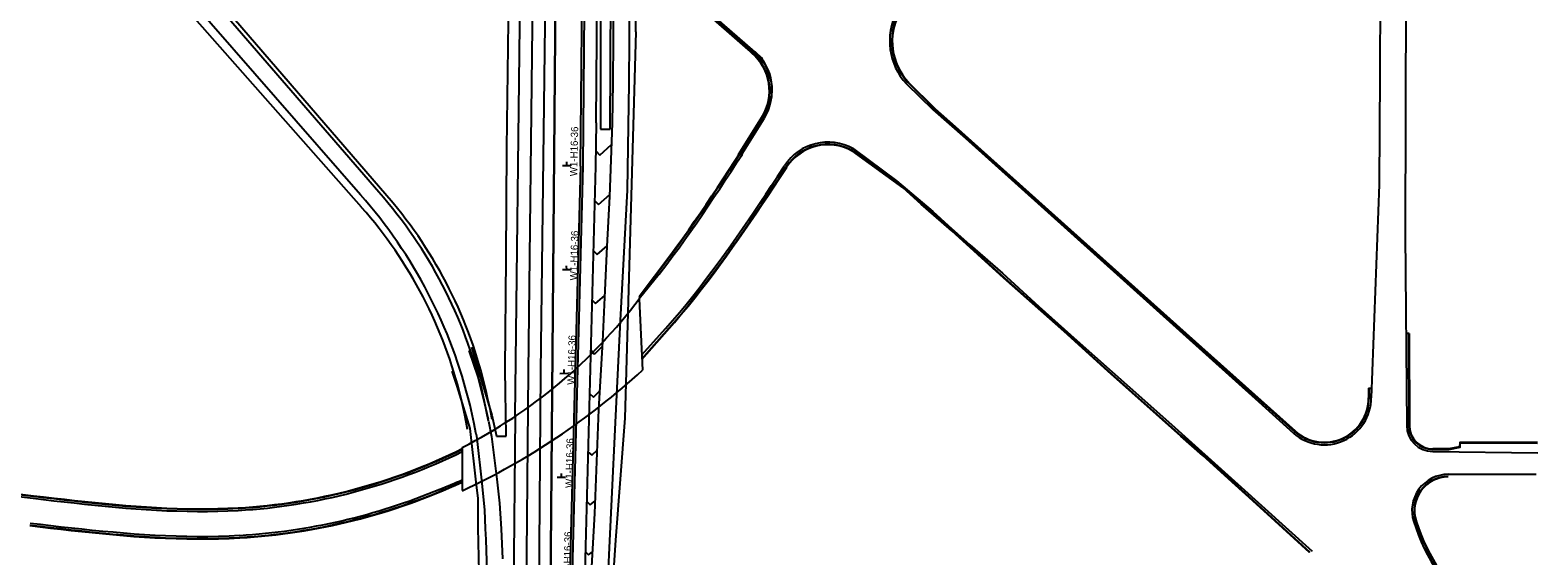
# Model space of a CAD drawing. Extents: x 1691089 to 1704871, y 694247 to 736350.
# Drawn here: x 1700893 to 1702343, y 708976 to 709482 of the extents above; entities that cross this region are included whole.
import ezdxf

# ---------------------------------------------------------------- set-up
doc = ezdxf.new("R2010")
doc.units = 0
for name, color, linetype in [('BR_X_Slab_Object', 7, 'Continuous'), ('MT_P_Channelizing_Line', 7, 'Continuous'), ('MT_P_Drums', 7, 'Continuous'), ('MT_P_Edge_Line', 7, 'Continuous'), ('PM_X_Channelizing_Line', 7, 'Continuous'), ('PM_X_Chevron_Line', 7, 'Continuous'), ('PM_X_CL_Dashed', 7, 'Continuous'), ('PM_X_Edge_Line', 7, 'Continuous'), ('PV_X_Curb', 7, 'Continuous'), ('PV_X_EOP', 7, 'Continuous'), ('PV_X_Shoulder', 7, 'Continuous'), ('RW_X_CL', 7, 'Continuous'), ('SC_Scratch1', 7, 'Continuous'), ('SC_Scratch3', 7, 'Continuous'), ('SN_P_Signs', 7, 'Continuous')]:
    doc.layers.add(name, color=color, linetype=linetype)

msp = doc.modelspace()

# ---------------------------------------------------------------- linework, layer by layer
at = {"layer": 'BR_X_Slab_Object'}
for p, q in [((1701478.8, 709223.9), (1701481.8, 709155.1)), ((1701308.5, 709080.8), (1701308.4, 709039.4))]:
    msp.add_line(p, q, dxfattribs=at)
for centre, radius, start, end in [((1701087.2, 709517), 489.1, 296.9039, 323.1906), ((1701022.3, 709653.8), 678.1, 294.9545, 312.6565)]:
    msp.add_arc(centre, radius, start, end, dxfattribs=at)
at = {"layer": 'MT_P_Channelizing_Line'}
for p, q in [((1701437.2, 709393.1), (1701436.8, 709351.4)), ((1701436.8, 709351.4), (1701426.4, 708961.4))]:
    msp.add_line(p, q, dxfattribs=at)
at = {"layer": 'MT_P_Drums'}
for q in [(1701430.3, 710278.4), (1701411.9, 708961.6)]:
    msp.add_line((1701422.3, 709351.5), q, dxfattribs=at)
at = {"layer": 'MT_P_Edge_Line'}
msp.add_line((1701437.2, 709393.1), (1701444.8, 710278.3), dxfattribs=at)
msp.add_lwpolyline([(1701414.4, 708961.6), (1701424.8, 709351.5), (1701474.5, 715147.9), (1701474.6, 715157.9), (1701474.7, 715167.9), (1701474.8, 715177.9), (1701474.9, 715187.9), (1701474.9, 715198), (1701475, 715208), (1701475, 715218), (1701475, 715228.1), (1701475, 715238.2), (1701475, 715248.3), (1701474.9, 715258.3), (1701474.8, 715268.4), (1701474.7, 715278.5), (1701474.5, 715288.6), (1701474.3, 715298.7), (1701474.1, 715308.8), (1701473.8, 715318.9), (1701473.5, 715329), (1701473.2, 715339.2), (1701472.7, 715349.3), (1701472.7, 715349.4)], dxfattribs=at)
at = {"layer": 'PM_X_Channelizing_Line'}
for p, q in [((1701445.7, 709225.1), (1701447.9, 709274.2)), ((1701443.7, 709182.7), (1701445.7, 709225.1)), ((1701439.9, 709117.3), (1701443.7, 709182.7)), ((1701435.9, 709017.3), (1701439.9, 709117.3)), ((1701359.3, 709111), (1701357.3, 708878.3)), ((1701336.5, 709091.3), (1701341.9, 709050.1)), ((1701341.9, 709050.1), (1701344.4, 709027.2)), ((1701344.4, 709027.2), (1701345.8, 709002.3)), ((1701431.8, 708942.4), (1701435.9, 709017.3)), ((1701345.8, 709002.3), (1701347.3, 708973.4))]:
    msp.add_line(p, q, dxfattribs=at)
msp.add_lwpolyline([(1701447.9, 709274.2), (1701450.3, 709322.3), (1701453, 709393)], dxfattribs=at)
at = {"layer": 'PM_X_Chevron_Line'}
for p, q in [((1701437, 709366.1), (1701440.8, 709362.2)), ((1701440.8, 709362.2), (1701452.2, 709372.3)), ((1701439.5, 709314.7), (1701450.4, 709324.2)), ((1701435.9, 709318.2), (1701439.5, 709314.7)), ((1701434.6, 709269.9), (1701438.3, 709266.4)), ((1701438.3, 709266.4), (1701447.9, 709274.9)), ((1701433.4, 709222.5), (1701436.8, 709219.2)), ((1701436.8, 709219.2), (1701445.8, 709226.9)), ((1701432.1, 709174.6), (1701435.6, 709170.5)), ((1701435.6, 709170.5), (1701443.4, 709178.2)), ((1701431, 709132.7), (1701434.6, 709129.2)), ((1701434.6, 709129.2), (1701441, 709135.6)), ((1701429.4, 709076.6), (1701433, 709073.3)), ((1701433, 709073.3), (1701438.4, 709078.1)), ((1701428.2, 709028.6), (1701431.4, 709025.4)), ((1701431.4, 709025.4), (1701436.4, 709029.5)), ((1701426.9, 708980.4), (1701429.9, 708977.4)), ((1701429.9, 708977.4), (1701433.9, 708980.3))]:
    msp.add_line(p, q, dxfattribs=at)
at = {"layer": 'PM_X_CL_Dashed'}
for p, q in [((1701376.2, 709513.9), (1701371.9, 709153.6)), ((1701371.9, 709153.6), (1701369.4, 708873))]:
    msp.add_line(p, q, dxfattribs=at)
at = {"layer": 'PM_X_Edge_Line'}
for p, q in [((1701453.6, 709431.6), (1701455.3, 709652.5)), ((1701469, 709431.5), (1701470.7, 709652.4)), ((1701359.3, 709111), (1701364.2, 709514)), ((1701388.2, 709513.8), (1701383.9, 709153.6)), ((1701453, 709393), (1701453.6, 709431.7)), ((1701467.3, 709328.4), (1701469, 709431.5)), ((1701460.7, 709202.8), (1701467.3, 709328.4)), ((1701457.3, 709131.3), (1701460.7, 709202.8)), ((1701383.9, 709153.6), (1701381.4, 708873)), ((1701451.1, 709004.3), (1701457.3, 709131.3)), ((1701333.9, 709106.2), (1701336.5, 709091.3)), ((1701444.7, 708876.8), (1701451.1, 709004.3))]:
    msp.add_line(p, q, dxfattribs=at)
msp.add_lwpolyline([(1701321.9, 709093.5), (1701322.4, 709089.4), (1701327.2, 709046.4), (1701328.5, 709033.1), (1701329.9, 709020.8), (1701330.6, 709002.3), (1701331.2, 708992.2), (1701332.4, 708950.8), (1701333.5, 708881.3), (1701334.1, 708822.9), (1701336, 708716.7), (1701337.6, 708568.1), (1701339.8, 708456.3), (1701343, 708267.7), (1701345.1, 708154.5), (1701348.7, 707936.7), (1701349.3, 707853.3), (1701350.4, 707631.1), (1701349.9, 707475), (1701348.9, 707313), (1701348.7, 707061.8)], dxfattribs=at)
at = {"layer": 'PV_X_Curb'}
for p, q in [((1701574.3, 709362.8), (1701596.7, 709398.7)), ((1701574.7, 709362.6), (1701597.1, 709398.4)), ((1701613.3, 709340.3), (1701620.1, 709350.7)), ((1701613.7, 709340), (1701620.7, 709350.5)), ((1702219.1, 709190.5), (1702216.6, 709190.4)), ((1702180.2, 709137.7), (1702180.2, 709128.4)), ((1702180.2, 709137.7), (1702182.7, 709137.7)), ((1702180.7, 709137.7), (1702180.7, 709128.4)), ((1700681.9, 709059.5), (1700896, 709034.3)), ((1700681.9, 709059), (1700896, 709033.8))]:
    msp.add_line(p, q, dxfattribs=at)
for points in [[(1701504.5, 709532.7), (1701595.7, 709453)], [(1701504.8, 709533), (1701596, 709453.4)], [(1701737.2, 709432.2), (1701763.5, 709406.1), (1701782.5, 709388.9), (1702004.6, 709189.9), (1702109.4, 709095.9)], [(1702109.8, 709096.3), (1702004.9, 709190.3), (1701782.8, 709389.2), (1701763.8, 709406.4), (1701737.5, 709432.5)], [(1701478.7, 709226), (1701509.2, 709266.6), (1701515, 709274.4), (1701520.7, 709282.3), (1701526.3, 709290.3), (1701531.9, 709298.4), (1701537.5, 709306.5), (1701543, 709314.6), (1701548.5, 709322.8), (1701554, 709331.1), (1701559.4, 709339.4), (1701564.9, 709347.7), (1701570.3, 709356), (1701575.8, 709364.4)], [(1701478.7, 709225.2), (1701509.6, 709266.3), (1701515.4, 709274.1), (1701521.1, 709282.1), (1701526.8, 709290), (1701532.4, 709298.1), (1701537.9, 709306.2), (1701543.4, 709314.4), (1701548.9, 709322.6), (1701554.4, 709330.8), (1701559.9, 709339.1), (1701565.3, 709347.4), (1701570.8, 709355.8), (1701576.2, 709364.1)], [(1702123.5, 708979.6), (1702090.4, 709009.7), (1702068.9, 709029.3), (1702048.9, 709047.5), (1702020.8, 709073), (1701999.7, 709091.6), (1701929.3, 709154.2), (1701887.4, 709192.2), (1701829.5, 709243.6), (1701779.5, 709289.2), (1701749.8, 709315), (1701732.5, 709330.7), (1701683.5, 709366.1)], [(1701683.8, 709366.5), (1701732.8, 709331.1), (1701750.1, 709315.3), (1701779.8, 709289.6), (1701829.9, 709244), (1701887.7, 709192.5), (1701929.6, 709154.6), (1702000, 709092), (1702021.2, 709073.3), (1702049.2, 709047.9), (1702069.2, 709029.7), (1702090.8, 709010.1), (1702123.8, 708980)], [(1701481.3, 709166.2), (1701512.2, 709201.5), (1701518.9, 709209.2), (1701525.4, 709217.1), (1701531.7, 709225), (1701538, 709233), (1701544.2, 709241), (1701550.3, 709249.2), (1701556.3, 709257.3), (1701562.3, 709265.5), (1701568.1, 709273.7), (1701573.9, 709282), (1701579.6, 709290.3), (1701585.3, 709298.6), (1701591, 709306.9), (1701596.6, 709315.3), (1701602.2, 709323.6), (1701607.7, 709331.9), (1701613.3, 709340.3)], [(1701481.3, 709165.5), (1701512.6, 709201.1), (1701519.2, 709208.9), (1701525.7, 709216.8), (1701532.1, 709224.7), (1701538.4, 709232.7), (1701544.6, 709240.7), (1701550.7, 709248.9), (1701556.7, 709257), (1701562.7, 709265.2), (1701568.5, 709273.4), (1701574.3, 709281.7), (1701580.1, 709290), (1701585.7, 709298.3), (1701591.4, 709306.6), (1701597, 709315), (1701602.6, 709323.3), (1701608.1, 709331.6), (1701613.7, 709340)], [(1702218.6, 709190.4), (1702218.9, 709101.8)], [(1702219.1, 709190.5), (1702219.4, 709101.9)], [(1702342.7, 709085.4), (1702286.4, 709085.6), (1702267.9, 709085.6), (1702267.8, 709081.4), (1702257.4, 709079.4), (1702242, 709079.4)], [(1702242, 709078.9), (1702257.5, 709078.9), (1702268.2, 709081), (1702268.4, 709085.1), (1702286.4, 709085.1), (1702342.7, 709084.9)], [(1700896, 709034.3), (1700905.9, 709033.2), (1700915.9, 709032), (1700925.8, 709030.9), (1700935.7, 709029.8), (1700945.5, 709028.7), (1700955.4, 709027.7), (1700965.3, 709026.7), (1700975.2, 709025.8), (1700985, 709024.9), (1700994.9, 709024.2), (1701004.7, 709023.5), (1701014.5, 709022.9), (1701024.4, 709022.4), (1701034.2, 709022.1), (1701044, 709021.8), (1701053.8, 709021.7), (1701063.6, 709021.7), (1701073.4, 709021.9), (1701083.1, 709022.2), (1701093, 709022.7)], [(1700896, 709033.8), (1700905.9, 709032.7), (1700915.8, 709031.5), (1700925.7, 709030.4), (1700935.6, 709029.3), (1700945.5, 709028.2), (1700955.4, 709027.2), (1700965.2, 709026.2), (1700975.1, 709025.3), (1700985, 709024.4), (1700994.8, 709023.7), (1701004.7, 709023), (1701014.5, 709022.4), (1701024.3, 709021.9), (1701034.2, 709021.6), (1701044, 709021.3), (1701053.8, 709021.2), (1701063.6, 709021.2), (1701073.4, 709021.4), (1701083.2, 709021.7), (1701093, 709022.2)], [(1700892.6, 709005.5), (1700902.6, 709004.4), (1700912.5, 709003.2), (1700922.5, 709002.1), (1700932.5, 709000.9), (1700942.5, 708999.9), (1700952.5, 708998.8), (1700962.5, 708997.8), (1700972.6, 708996.9), (1700982.6, 708996), (1700992.7, 708995.2), (1701002.8, 708994.5), (1701013, 708993.9), (1701023.1, 708993.4), (1701033.3, 708993.1), (1701043.5, 708992.8), (1701053.7, 708992.7), (1701063.9, 708992.7), (1701074.1, 708992.9), (1701084.3, 708993.2), (1701094.4, 708993.7)], [(1700892.7, 709006), (1700902.6, 709004.9), (1700912.6, 709003.7), (1700922.5, 709002.6), (1700932.5, 709001.4), (1700942.5, 709000.4), (1700952.5, 708999.3), (1700962.6, 708998.3), (1700972.6, 708997.4), (1700982.7, 708996.5), (1700992.8, 708995.7), (1701002.9, 708995), (1701013, 708994.4), (1701023.1, 708993.9), (1701033.3, 708993.6), (1701043.5, 708993.3), (1701053.7, 708993.2), (1701063.9, 708993.2), (1701074.1, 708993.4), (1701084.3, 708993.7), (1701094.4, 708994.2)]]:
    msp.add_lwpolyline(points, dxfattribs=at)
for centre, radius, start, end in [((1701779.6, 709471.7), 58, 152.245, 223.002), ((1701779.6, 709471.7), 57.5, 152.245, 223.002), ((1701556.4, 709423.9), 47.5, 327.9635, 49.815), ((1701556.4, 709423.9), 48, 327.9635, 49.8927), ((1701559, 709425.8), 47.5, 326.9156, 48.7671), ((1701660.3, 709324.6), 48, 60.7984, 146.977), ((1701660.3, 709324.6), 47.5, 60.8165, 146.8745), ((1702137.7, 709128.3), 43, 228.858, 0.2254), ((1702137.7, 709128.3), 42.5, 228.858, 0.2562), ((1702241.9, 709101.9), 23, 180.2308, 270.2308), ((1702241.9, 709101.9), 22.5, 180.2308, 270.2308), ((1701060.8, 709580.2), 558.5, 273.2963, 296.3321), ((1701060.8, 709580.2), 559, 273.2963, 296.3066), ((1701060.8, 709580.2), 587, 273.2963, 294.9549), ((1701060.8, 709580.2), 587.5, 273.2963, 294.932), ((1702256.9, 709019.9), 33, 90.1804, 197.7824), ((1702256.9, 709019.9), 32.5, 90.1804, 197.7824), ((1702416, 709070.7), 200, 197.732, 228.7856), ((1702416, 709070.7), 199.5, 197.732, 228.7856)]:
    msp.add_arc(centre, radius, start, end, dxfattribs=at)
at = {"layer": 'PV_X_EOP'}
for p, q in [((1701446.5, 715148.2), (1701323.4, 700783.8)), ((1701446.5, 715148.2), (1701323.4, 700783.8)), ((1701446.5, 715148.2), (1701323.4, 700783.8)), ((1701446.5, 715148.2), (1701323.4, 700783.8)), ((1701441.6, 709583.3), (1701441.6, 709387.2)), ((1701450.8, 709387.2), (1701451.9, 709574.3)), ((1701210.7, 709323.9), (1701047, 709511.5)), ((1701228.2, 709326.4), (1701069.3, 709510.2)), ((1701576.4, 709361.5), (1701598.8, 709397.4)), ((1701441.6, 709387.2), (1701450.8, 709387.2)), ((1701611.6, 709341.4), (1701618.6, 709351.8)), ((1701497.8, 709247.5), (1701478.8, 709223.9)), ((1700681.6, 709057), (1700895.7, 709031.8))]:
    msp.add_line(p, q, dxfattribs=at)
for points in [[(1702236.5, 711634.6), (1702234.2, 711544.9), (1702233.5, 711441.5), (1702227.9, 711277.7), (1702226.4, 711103), (1702225.5, 711002.5), (1702224.4, 710870.4), (1702223.7, 710704.5), (1702222.7, 710562.6), (1702221.6, 710366.2), (1702220.3, 710180.7), (1702218.7, 709978.6), (1702217.3, 709834.2), (1702216.7, 709707.1), (1702216, 709519), (1702215.3, 709285.9), (1702216.9, 709101.8)], [(1702196.2, 711603), (1702197.1, 711593), (1702198.4, 711561.8), (1702203.2, 711284.2), (1702203.9, 711216.5), (1702203.6, 711180.6), (1702203.3, 711141.8), (1702200.2, 710747.3), (1702198.5, 710484), (1702195.7, 710156.1), (1702195.4, 710077.5), (1702194.4, 709958.4), (1702193.1, 709774.7), (1702191.7, 709594.1), (1702191.1, 709439.8), (1702190.5, 709333.9), (1702182.7, 709128.4)], [(1701506.2, 709534.5), (1701597.3, 709454.9)], [(1701735.7, 709430.8), (1701761.2, 709406), (1701792.4, 709378.3), (1702074.3, 709124.9), (1702108.1, 709094.4)], [(1701497.8, 709247.5), (1701505.4, 709257.3), (1701511.2, 709265.1), (1701517, 709273), (1701522.7, 709280.9), (1701528.4, 709288.9), (1701534, 709297), (1701539.6, 709305.1), (1701545.1, 709313.2), (1701550.6, 709321.5), (1701556.1, 709329.7), (1701561.5, 709338), (1701567, 709346.3), (1701572.4, 709354.7), (1701577.9, 709363)], [(1701684.7, 709368.2), (1701726.2, 709337.5), (1701761, 709308), (1701776, 709294.3), (1701796.8, 709275.7), (1701828.2, 709248.4), (1701863.1, 709216.5), (1701899.6, 709183.8), (1701950.5, 709138.3), (1701990.8, 709102.7), (1702054.4, 709045.4), (1702125.8, 708980.8)], [(1701481.1, 709169.9), (1701504, 709195.1), (1701510.7, 709202.8), (1701517.3, 709210.5), (1701523.8, 709218.4), (1701530.2, 709226.3), (1701536.5, 709234.2), (1701542.6, 709242.3), (1701548.7, 709250.3), (1701554.7, 709258.5), (1701560.6, 709266.7), (1701566.5, 709274.9), (1701572.3, 709283.1), (1701578, 709291.4), (1701583.7, 709299.7), (1701589.3, 709308), (1701594.9, 709316.4), (1701600.5, 709324.7), (1701606, 709333), (1701611.6, 709341.4)], [(1701333.9, 709106.2), (1701329.7, 709126.3), (1701327.6, 709135.3)], [(1701321.9, 709093.5), (1701321.7, 709094.7), (1701320, 709103.6), (1701318.1, 709112.5), (1701316, 709121.4)], [(1702242, 709076.9), (1702343, 709075.7)], [(1702256.8, 709054.9), (1702341.5, 709055.2)], [(1700895.7, 709031.8), (1700905.7, 709030.7), (1700915.6, 709029.5), (1700925.5, 709028.4), (1700935.4, 709027.3), (1700945.3, 709026.2), (1700955.2, 709025.2), (1700965, 709024.2), (1700974.9, 709023.3), (1700984.8, 709022.4), (1700994.7, 709021.7), (1701004.5, 709021), (1701014.4, 709020.4), (1701024.3, 709019.9), (1701034.1, 709019.6), (1701044, 709019.3), (1701053.8, 709019.2), (1701063.6, 709019.2), (1701073.4, 709019.4), (1701083.2, 709019.7), (1701093.1, 709020.2)], [(1700892.9, 709008), (1700902.9, 709006.8), (1700912.8, 709005.7), (1700922.8, 709004.5), (1700932.7, 709003.4), (1700942.7, 709002.3), (1700952.7, 709001.3), (1700962.8, 709000.3), (1700972.8, 708999.4), (1700982.8, 708998.5), (1700992.9, 708997.7), (1701003, 708997), (1701013.1, 708996.4), (1701023.2, 708995.9), (1701033.4, 708995.6), (1701043.5, 708995.3), (1701053.7, 708995.2), (1701063.8, 708995.2), (1701074, 708995.4), (1701084.2, 708995.7), (1701094.3, 708996.2)]]:
    msp.add_lwpolyline(points, dxfattribs=at)
for centre, radius, start, end in [((1701779.6, 709471.7), 60, 152.245, 223.002), ((1701556.4, 709423.9), 50, 327.9635, 49.9558), ((1701660.3, 709324.6), 50, 60.8165, 146.958), ((1700856.4, 709010.9), 472.7, 13.5158, 41.458), ((1700893.8, 709031), 446.2, 13.5158, 41.458), ((1702137.7, 709128.3), 45, 228.8768, 0.2308), ((1702241.9, 709101.9), 25, 180.2308, 270.2308), ((1701060.8, 709580.2), 561, 273.2963, 296.205), ((1701020.3, 709718.5), 728.4, 291.4716, 293.3013), ((1702256.9, 709019.9), 35, 90.1804, 197.7824), ((1701060.8, 709580.2), 585, 273.2963, 292.7424), ((1702416.6, 709070.9), 202.6, 197.732, 228.7856)]:
    msp.add_arc(centre, radius, start, end, dxfattribs=at)
at = {"layer": 'PV_X_Shoulder'}
for p, q in [((1701351.5, 709368.8), (1701355.4, 709659.4)), ((1701475.6, 709480.8), (1701476.3, 709552.8)), ((1701242.1, 709315.8), (1701066.5, 709519.7)), ((1701211.7, 709311.9), (1701051.2, 709493.5)), ((1701475.6, 709480.8), (1701464.9, 709109.1)), ((1701475.6, 709480.8), (1701464.9, 709109.1)), ((1701350.7, 709262.8), (1701351.5, 709368.8)), ((1701350.7, 709262.8), (1701351.5, 709368.8)), ((1701349.7, 709155.9), (1701350.7, 709262.8)), ((1701349.7, 709155.9), (1701350.7, 709262.8)), ((1701317.5, 709177.4), (1701337, 709111.8)), ((1701317.5, 709177.4), (1701337, 709111.8)), ((1701303.6, 709139.7), (1701298.7, 709154.3)), ((1701303.6, 709139.7), (1701298.7, 709154.3)), ((1701350.6, 709091.6), (1701349.7, 709155.9)), ((1701350.6, 709091.6), (1701349.7, 709155.9)), ((1701316, 709099.1), (1701303.6, 709139.7)), ((1701316, 709099.1), (1701303.6, 709139.7)), ((1701337, 709111.8), (1701341.5, 709091.5)), ((1701337, 709111.8), (1701341.5, 709091.5)), ((1701464.9, 709109.1), (1701455.9, 708991.5)), ((1701464.9, 709109.1), (1701455.9, 708991.5)), ((1701322.2, 709044.3), (1701316, 709099.1)), ((1701322.2, 709044.3), (1701316, 709099.1)), ((1701341.5, 709091.5), (1701350.6, 709091.6)), ((1701341.5, 709091.5), (1701350.6, 709091.6)), ((1701323.7, 709031.9), (1701322.2, 709044.3)), ((1701323.7, 709031.9), (1701322.2, 709044.3)), ((1701323.9, 709003.3), (1701323.7, 709031.9)), ((1701323.9, 709003.3), (1701323.7, 709031.9)), ((1701324.7, 708961.1), (1701323.9, 709003.3)), ((1701324.7, 708961.1), (1701323.9, 709003.3)), ((1701455.9, 708991.5), (1701451.1, 708919.9)), ((1701455.9, 708991.5), (1701451.1, 708919.9))]:
    msp.add_line(p, q, dxfattribs=at)
for points in [[(1701313.6, 709098), (1701313, 709101.5), (1701311.3, 709110.3), (1701309.4, 709119.1), (1701307.4, 709127.9)], [(1701337.4, 709107.6), (1701334.9, 709119.4), (1701332.9, 709128.5)]]:
    msp.add_lwpolyline(points, dxfattribs=at)
for centre, radius, start, end in [((1700889.8, 709027.5), 429.5, 13.5158, 41.458), ((1700911.1, 709039.7), 431, 11.886, 39.8282)]:
    msp.add_arc(centre, radius, start, end, dxfattribs=at)
at = {"layer": 'RW_X_CL'}
msp.add_line((1701323.4, 700783.8), (1701446.5, 715148.2), dxfattribs=at)
at = {"layer": 'SC_Scratch3'}
for p, q in [((1701314.7, 709174), (1701323.4, 709148.6)), ((1701323.4, 709148.6), (1701328.7, 709128.5)), ((1701328.7, 709128.5), (1701333.4, 709107.9))]:
    msp.add_line(p, q, dxfattribs=at)
at = {"layer": 'SN_P_Signs'}
for p, q in [((1701413, 709351.8), (1701405, 709351.7)), ((1701409, 709351.8), (1701409, 709355.8)), ((1701413, 709251.8), (1701405, 709251.7)), ((1701409, 709251.7), (1701408.9, 709255.7)), ((1701410.4, 709151.8), (1701402.4, 709151.7)), ((1701406.4, 709151.8), (1701406.4, 709155.8)), ((1701407.9, 709051.8), (1701399.9, 709051.8)), ((1701403.9, 709051.8), (1701403.9, 709055.8))]:
    msp.add_line(p, q, dxfattribs=at)

# ---------------------------------------------------------------- texts
at = {"layer": 'SC_Scratch1'}
for p in [(1701419, 709341.7), (1701419.1, 709241.5), (1701416.6, 709141), (1701414.7, 709041.7), (1701412.7, 708951.9)]:
    msp.add_text('W1-H16-36', height=7, rotation=88.6903, dxfattribs=at).set_placement(p)

doc.saveas('drawing.dxf')
